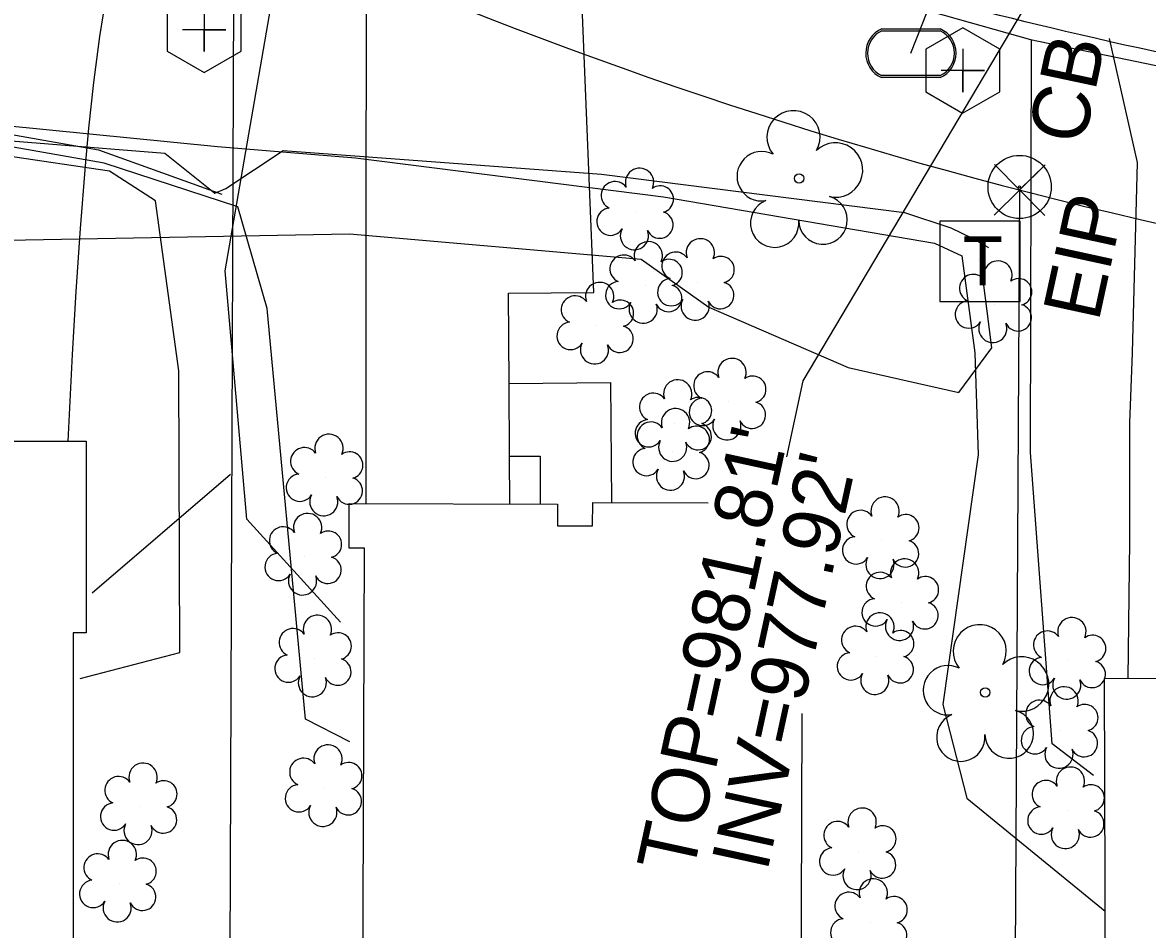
# Model space of a CAD drawing. Extents: x 1614427 to 1617186, y 896524 to 905462.
# Drawn here: x 1616409.1 to 1616487.6, y 901599.9 to 901663.2 of the extents above; entities that cross this region are included whole.
import ezdxf

# ---------------------------------------------------------------- set-up
doc = ezdxf.new("R2010")
doc.units = 0
for name, color, linetype in [('Exist Building', 7, 'Continuous'), ('Exist Other Culture Area Outline', 7, 'Continuous'), ('Exist Property Corner CELL', 7, 'Continuous'), ('Exist Property Iron Pin CELL', 7, 'Continuous'), ('Exist Property Iron Pin Text', 7, 'Continuous'), ('Exist Property Line', 7, 'Continuous'), ('Exist Right of Way Line', 7, 'Continuous'), ('Exist Roads Curbs', 7, 'Continuous'), ('Exist Roads EOP', 7, 'Continuous'), ('Exist Roads EOP Other', 7, 'Continuous'), ('Exist Structure Minor Catch Basin Leader', 7, 'Continuous'), ('Exist Structure Minor Catch Basin Text', 7, 'Continuous'), ('Exist Structure Minor Catch Basin Top Elevation', 7, 'Continuous'), ('Exist Structure Minor Pipes RCP 18 Inch Invert', 7, 'Continuous'), ('Exist Utilities Gas UG Line SUE LOS B', 7, 'Continuous'), ('Exist Utilities Power UG Cable SUE LOS B', 7, 'Continuous'), ('Exist Utilities Sanitary Sewer Clean-Out CELL', 7, 'Continuous'), ('Exist Utilities Telephone Pedestal CELL', 7, 'Continuous'), ('Exist Utilities Telephone UG FO SUE LOS B', 7, 'Continuous'), ('Exist Utilities TV UG Cable SUE LOS B', 7, 'Continuous'), ('Exist Utilities Water Meter CELL', 7, 'Continuous'), ('Exist Utilities Water UG Line SUE LOS B', 7, 'Continuous'), ('Exist Vegetation Shrub CELL', 7, 'Continuous'), ('Exist Vegetation Tree CELL', 7, 'Continuous')]:
    doc.layers.add(name, color=color, linetype=linetype)

# ---------------------------------------------------------------- blocks, each defined once
blk = doc.blocks.new('EXIST PROPERTY IRON PIN')
at = {"layer": 'Exist Property Iron Pin CELL'}
for radius in [0.0441, 0.00141]:
    blk.add_circle((0, 0), radius, dxfattribs=at)
blk = doc.blocks.new('EXIST UTILITIES SANITARY SEWER CLEAN-OUT')
at = {"layer": 'Exist Utilities Sanitary Sewer Clean-Out CELL'}
blk.add_line((0, 0), (0, 0), dxfattribs=at)
blk.add_lwpolyline([(-0.0516, 0.0299), (-0.0517, -0.0297), (-0.0001, -0.0596), (0.0516, -0.0299), (0.0517, 0.0297), (0.0001, 0.0596)], close=True, dxfattribs=at)
blk.add_lwpolyline([(0, 0.0302), (0, -0.0302), (0, 0), (0.0302, 0), (-0.0302, 0)], dxfattribs=at)
blk = doc.blocks.new('EXIST UTILITIES TELEPHONE PEDESTAL')
at = {"layer": 'Exist Utilities Telephone Pedestal CELL'}
blk.add_line((0, 0), (0, 0), dxfattribs=at)
blk.add_lwpolyline([(-0.0545, -0.0565), (0.0574, -0.0565), (0.0574, 0.0554), (-0.0545, 0.0554), (-0.0545, -0.0565)], dxfattribs=at)
blk.add_text('T', height=0.0684, dxfattribs=at).set_placement((-0.0226, -0.0343))
blk = doc.blocks.new('EXIST UTILITIES WATER METER')
at = {"layer": 'Exist Utilities Water Meter CELL'}
blk.add_line((0, 0), (0, 0), dxfattribs=at)
for points in [[(-0.0408, 0.034), (0.0408, 0.034)], [(-0.0408, 0.0312), (0.0408, 0.0312)], [(0.0408, -0.0312), (-0.0413, -0.0312)], [(0.0408, -0.034), (-0.0413, -0.034)]]:
    blk.add_lwpolyline(points, dxfattribs=at)
for centre, radius, start, end in [((-0.0261, -0.0001), 0.0371, 113.178, 245.9794), ((0.0259, 0), 0.0371, 293.6483, 66.3084), ((-0.0259, -0.0001), 0.0347, 115.3009, 243.7824), ((0.0261, 0), 0.0345, 295.1272, 64.8728)]:
    blk.add_arc(centre, radius, start, end, dxfattribs=at)

msp = doc.modelspace()

# ---------------------------------------------------------------- linework, layer by layer
at = {"layer": 'Exist Building'}
for points in [[(1616394.898, 901627.651), (1616398.83, 901627.651), (1616398.829, 901633.968), (1616413.521, 901633.969), (1616413.522, 901620.575), (1616412.606, 901620.575), (1616412.608, 901591.698), (1616385.935, 901591.696), (1616385.933, 901610.332)], [(1616463.489, 901614.953), (1616463.395, 901587.068), (1616457.292, 901587.088), (1616457.264, 901578.691), (1616431.849, 901578.776), (1616431.883, 901588.687), (1616432.819, 901588.684), (1616432.946, 901626.485), (1616431.868, 901626.489), (1616431.878, 901629.618), (1616446.423, 901629.569), (1616446.418, 901628.051), (1616448.876, 901628.043), (1616448.881, 901629.683), (1616456.949, 901629.656)]]:
    msp.add_lwpolyline(points, dxfattribs=at)
msp.add_lwpolyline([(1616517.458, 901617.54), (1616517.599, 901573.704), (1616484.754, 901573.599), (1616484.614, 901617.397), (1616496.062, 901617.434), (1616496.048, 901621.76), (1616517.306, 901621.828), (1616517.32, 901617.539)], close=True, dxfattribs=at)
at = {"layer": 'Exist Other Culture Area Outline'}
for points in [[(1616443.048, 901637.997), (1616450.123, 901638.046), (1616450.194, 901629.679)], [(1616443.075, 901632.906), (1616445.208, 901632.905), (1616445.224, 901629.573)]]:
    msp.add_lwpolyline(points, dxfattribs=at)
at = {"layer": 'Exist Property Corner CELL'}
msp.add_line((1616478.69, 901651.495), (1616478.69, 901651.495), dxfattribs=at)
msp.add_lwpolyline([(1616476.932, 901653.273), (1616480.448, 901649.717), (1616478.69, 901651.495), (1616480.467, 901653.253), (1616476.912, 901649.737)], dxfattribs=at)
at = {"layer": 'Exist Property Line'}
for p, q in [((1616423.205, 901496.843), (1616423.837, 901670.831)), ((1616478.69, 901651.495), (1616477.825, 901496.627))]:
    msp.add_line(p, q, dxfattribs=at)
at = {"layer": 'Exist Right of Way Line'}
msp.add_arc((1616560.484, 901967.642), 326.557, 246.2087, 268.51667, dxfattribs=at)
at = {"layer": 'Exist Roads Curbs'}
msp.add_spline([(1616576.436, 901651.141), (1616560.362, 901651.873), (1616541.572, 901653.197), (1616514.262, 901656.474), (1616480.87, 901662.803), (1616452.549, 901670.884), (1616427.974, 901679.501)], degree=3, dxfattribs=at)
at = {"layer": 'Exist Roads EOP'}
msp.add_spline([(1616600.703, 901615.071), (1616596.491, 901640.707), (1616577.816, 901651.88), (1616577.758, 901653.582), (1616560.382, 901654.399), (1616541.66, 901655.742), (1616514.624, 901658.966), (1616481.568, 901665.456), (1616453.293, 901673.284), (1616429.007, 901681.848), (1616427.559, 901682.356), (1616413.543, 901687.442), (1616400.429, 901690.536), (1616382.846, 901691.642), (1616359.811, 901688.156), (1616349.758, 901685.257), (1616334.537, 901681.299), (1616320.225, 901678.765)], degree=3, dxfattribs=at)
at = {"layer": 'Exist Roads EOP Other'}
for points in [[(1616412.253, 901633.969), (1616412.563, 901640.017), (1616412.82, 901644.408), (1616413.119, 901648.794), (1616413.462, 901653.175), (1616413.689, 901655.803), (1616414.047, 901659.005), (1616414.479, 901662.199), (1616414.984, 901665.385), (1616415.561, 901668.56), (1616416.086, 901671.026)], [(1616433.067, 901629.614), (1616433.076, 901644.726), (1616433.098, 901669.403)], [(1616443.093, 901629.58), (1616443.075, 901632.906), (1616443.048, 901637.997), (1616443.015, 901644.283), (1616448.973, 901644.349), (1616448.154, 901664.293)], [(1616486.283, 901617.402), (1616486.381, 901626.996), (1616486.398, 901635.24), (1616486.564, 901640.136), (1616486.917, 901653.403), (1616484.967, 901662.054)]]:
    msp.add_lwpolyline(points, dxfattribs=at)
at = {"layer": 'Exist Structure Minor Catch Basin Leader'}
msp.add_lwpolyline([(1616479.393, 901664.827), (1616463.567, 901638.167), (1616462.425, 901632.862)], dxfattribs=at)
at = {"layer": 'Exist Utilities Gas UG Line SUE LOS B'}
msp.add_line((1616413.941, 901623.385), (1616423.596, 901631.665), dxfattribs=at)
for points in [[(1616326.476, 901676.736), (1616348.676, 901680.409), (1616373.137, 901686.793), (1616383.025, 901688.182), (1616402.076, 901686.65), (1616424.003, 901679.778), (1616450.549, 901670.159), (1616479.448, 901661.996), (1616512.172, 901655.218), (1616540.791, 901649.287), (1616561.301, 901640.128), (1616569.634, 901633.987), (1616582.757, 901628.459), (1616598.916, 901622.957)], [(1616431.279, 901621.331), (1616424.74, 901628.52), (1616423.23, 901645.841), (1616426.723, 901666.015), (1616429.548, 901678.085)], [(1616483.844, 901610.622), (1616480.965, 901612.831), (1616479.461, 901633.18), (1616479.526, 901661.974)]]:
    msp.add_lwpolyline(points, dxfattribs=at)
at = {"layer": 'Exist Utilities Power UG Cable SUE LOS B'}
for points in [[(1616431.929, 901612.971), (1616428.819, 901614.563), (1616426.151, 901643.219), (1616424.095, 901650.319), (1616414.764, 901653.361), (1616392.769, 901657.217), (1616371.385, 901660.505), (1616355.218, 901660.133), (1616340.06, 901657.556), (1616322.037, 901656.408)], [(1616322.129, 901656.828), (1616339.438, 901657.54), (1616355.254, 901660.311), (1616371.586, 901660.692), (1616392.859, 901657.485), (1616422.684, 901654.528), (1616432.316, 901653.731), (1616453.833, 901651.02), (1616472.739, 901647.791), (1616474.659, 901646.901), (1616475.563, 901640.136), (1616475.797, 901633.012), (1616473.32, 901615.576), (1616475.015, 901609.049), (1616484.66, 901601.148)], [(1616413.087, 901617.407), (1616420.044, 901619.219), (1616419.981, 901638.866), (1616418.361, 901650.741), (1616415.145, 901652.817), (1616393.412, 901656.01), (1616371.662, 901659.29), (1616355.743, 901659.03), (1616340.12, 901656.384), (1616321.804, 901655.34)]]:
    msp.add_lwpolyline(points, dxfattribs=at)
at = {"layer": 'Exist Utilities Telephone UG FO SUE LOS B'}
msp.add_lwpolyline([(1616320.939, 901651.383), (1616362.887, 901649.358), (1616380.365, 901647.483), (1616431.909, 901648.438), (1616452.27, 901646.672), (1616456.985, 901643.309), (1616466.723, 901639.114), (1616474.447, 901637.354), (1616476.764, 901640.469), (1616475.96, 901646.691)], dxfattribs=at)
at = {"layer": 'Exist Utilities TV UG Cable SUE LOS B'}
for points in [[(1616322.594, 901658.961), (1616339.795, 901659.859), (1616360.734, 901661.282), (1616382.487, 901659.929), (1616414.384, 901654.293), (1616422.982, 901651.209)], [(1616322.652, 901659.227), (1616355.195, 901661.085), (1616371.732, 901661.161), (1616395.914, 901657.717), (1616402.743, 901655.366), (1616419.005, 901654.07), (1616422.504, 901651.267), (1616423.268, 901651.588), (1616427.27, 901654.253), (1616449.491, 901652.608), (1616470.665, 901649.916), (1616473.894, 901648.847), (1616475.375, 901648.133), (1616476.522, 901647.481)]]:
    msp.add_lwpolyline(points, dxfattribs=at)
at = {"layer": 'Exist Utilities Water UG Line SUE LOS B'}
msp.add_line((1616471.106, 901661.04), (1616476.068, 901673.701), dxfattribs=at)
at = {"layer": 'Exist Vegetation Shrub CELL'}
for p, q in [((1616451.925, 901649.987), (1616451.925, 901649.987)), ((1616452.538, 901644.858), (1616452.538, 901644.858)), ((1616456.17, 901645.065), (1616456.17, 901645.065)), ((1616476.949, 901643.511), (1616476.949, 901643.511)), ((1616449.139, 901642.015), (1616449.139, 901642.015)), ((1616458.382, 901636.712), (1616458.382, 901636.712)), ((1616454.597, 901635.219), (1616454.597, 901635.219)), ((1616454.44, 901633.208), (1616454.44, 901633.208)), ((1616430.237, 901631.422), (1616430.237, 901631.422)), ((1616469.071, 901627.042), (1616469.071, 901627.042)), ((1616428.752, 901625.891), (1616428.752, 901625.891)), ((1616470.436, 901622.719), (1616470.436, 901622.719)), ((1616429.436, 901618.791), (1616429.436, 901618.791)), ((1616468.712, 901618.953), (1616468.712, 901618.953)), ((1616482.113, 901618.625), (1616482.113, 901618.625)), ((1616481.566, 901613.794), (1616481.566, 901613.794)), ((1616430.171, 901609.741), (1616430.171, 901609.741)), ((1616417.264, 901608.467), (1616417.264, 901608.467)), ((1616482.01, 901608.189), (1616482.01, 901608.189)), ((1616467.47, 901605.329), (1616467.47, 901605.329)), ((1616415.807, 901603.07), (1616415.807, 901603.07)), ((1616468.25, 901600.387), (1616468.25, 901600.387))]:
    msp.add_line(p, q, dxfattribs=at)
for centre, radius, start, end in [((1616452.154, 901652.027), 0.99, 334.83907, 200.47174), ((1616450.442, 901651.114), 0.968, 35.89076, 245.42165), ((1616453.597, 901650.856), 0.929, 284.45672, 126.08612), ((1616450.124, 901649.282), 0.955, 95.10992, 327.95341), ((1616453.562, 901649.058), 0.937, 204.99133, 73.46012), ((1616451.796, 901648.303), 0.984, 151.27966, 21.38702), ((1616452.766, 901646.899), 0.99, 334.83907, 200.47174), ((1616456.398, 901647.106), 0.99, 334.83907, 200.47174), ((1616454.687, 901646.192), 0.968, 35.89076, 245.42165), ((1616451.055, 901645.985), 0.968, 35.89076, 245.42165), ((1616454.21, 901645.727), 0.929, 284.45672, 126.08612), ((1616457.842, 901645.934), 0.929, 284.45672, 126.08612), ((1616477.178, 901645.551), 0.99, 334.83907, 200.47174), ((1616475.467, 901644.637), 0.968, 35.89076, 245.42165), ((1616449.368, 901644.056), 0.99, 334.83907, 200.47174), ((1616450.737, 901644.154), 0.955, 95.10992, 327.95341), ((1616454.175, 901643.929), 0.937, 204.99133, 73.46012), ((1616454.369, 901644.361), 0.955, 95.10992, 327.95341), ((1616457.807, 901644.136), 0.937, 204.99133, 73.46012), ((1616478.621, 901644.379), 0.929, 284.45672, 126.08612), ((1616447.656, 901643.142), 0.968, 35.89076, 245.42165), ((1616450.811, 901642.884), 0.929, 284.45672, 126.08612), ((1616452.409, 901643.175), 0.984, 151.27966, 21.38702), ((1616456.041, 901643.382), 0.984, 151.27966, 21.38702), ((1616475.149, 901642.806), 0.955, 95.10992, 327.95341), ((1616478.586, 901642.582), 0.937, 204.99133, 73.46012), ((1616447.339, 901641.311), 0.955, 95.10992, 327.95341), ((1616450.776, 901641.086), 0.937, 204.99133, 73.46012), ((1616476.821, 901641.827), 0.984, 151.27966, 21.38702), ((1616449.01, 901640.332), 0.984, 151.27966, 21.38702), ((1616458.61, 901638.752), 0.99, 334.83907, 200.47174), ((1616456.899, 901637.838), 0.968, 35.89076, 245.42165), ((1616460.054, 901637.581), 0.929, 284.45672, 126.08612), ((1616454.826, 901637.26), 0.99, 334.83907, 200.47174), ((1616453.114, 901636.346), 0.968, 35.89076, 245.42165), ((1616456.581, 901636.007), 0.955, 95.10992, 327.95341), ((1616456.269, 901636.088), 0.929, 284.45672, 126.08612), ((1616454.668, 901635.248), 0.99, 334.83907, 200.47174), ((1616460.019, 901635.783), 0.937, 204.99133, 73.46012), ((1616452.796, 901634.515), 0.955, 95.10992, 327.95341), ((1616452.957, 901634.335), 0.968, 35.89076, 245.42165), ((1616458.253, 901635.028), 0.984, 151.27966, 21.38702), ((1616456.234, 901634.29), 0.937, 204.99133, 73.46012), ((1616456.112, 901634.077), 0.929, 284.45672, 126.08612), ((1616430.466, 901633.462), 0.99, 334.83907, 200.47174), ((1616454.468, 901633.536), 0.984, 151.27966, 21.38702), ((1616428.755, 901632.548), 0.968, 35.89076, 245.42165), ((1616431.909, 901632.291), 0.929, 284.45672, 126.08612), ((1616452.639, 901632.503), 0.955, 95.10992, 327.95341), ((1616456.077, 901632.279), 0.937, 204.99133, 73.46012), ((1616428.437, 901630.717), 0.955, 95.10992, 327.95341), ((1616431.874, 901630.493), 0.937, 204.99133, 73.46012), ((1616454.311, 901631.524), 0.984, 151.27966, 21.38702), ((1616430.109, 901629.738), 0.984, 151.27966, 21.38702), ((1616469.3, 901629.083), 0.99, 334.83907, 200.47174), ((1616467.589, 901628.169), 0.968, 35.89076, 245.42165), ((1616428.981, 901627.931), 0.99, 334.83907, 200.47174), ((1616470.743, 901627.911), 0.929, 284.45672, 126.08612), ((1616427.27, 901627.018), 0.968, 35.89076, 245.42165), ((1616430.424, 901626.76), 0.929, 284.45672, 126.08612), ((1616467.271, 901626.338), 0.955, 95.10992, 327.95341), ((1616470.709, 901626.113), 0.937, 204.99133, 73.46012), ((1616426.952, 901625.187), 0.955, 95.10992, 327.95341), ((1616430.389, 901624.962), 0.937, 204.99133, 73.46012), ((1616468.943, 901625.359), 0.984, 151.27966, 21.38702), ((1616470.665, 901624.759), 0.99, 334.83907, 200.47174), ((1616428.624, 901624.207), 0.984, 151.27966, 21.38702), ((1616468.953, 901623.845), 0.968, 35.89076, 245.42165), ((1616472.108, 901623.588), 0.929, 284.45672, 126.08612), ((1616468.636, 901622.014), 0.955, 95.10992, 327.95341), ((1616468.941, 901620.993), 0.99, 334.83907, 200.47174), ((1616472.073, 901621.79), 0.937, 204.99133, 73.46012), ((1616429.665, 901620.832), 0.99, 334.83907, 200.47174), ((1616470.308, 901621.035), 0.984, 151.27966, 21.38702), ((1616482.342, 901620.665), 0.99, 334.83907, 200.47174), ((1616427.954, 901619.918), 0.968, 35.89076, 245.42165), ((1616431.108, 901619.66), 0.929, 284.45672, 126.08612), ((1616467.23, 901620.08), 0.968, 35.89076, 245.42165), ((1616470.384, 901619.822), 0.929, 284.45672, 126.08612), ((1616480.631, 901619.751), 0.968, 35.89076, 245.42165), ((1616483.785, 901619.493), 0.929, 284.45672, 126.08612), ((1616427.636, 901618.087), 0.955, 95.10992, 327.95341), ((1616466.912, 901618.248), 0.955, 95.10992, 327.95341), ((1616470.349, 901618.024), 0.937, 204.99133, 73.46012), ((1616480.313, 901617.92), 0.955, 95.10992, 327.95341), ((1616431.074, 901617.862), 0.937, 204.99133, 73.46012), ((1616483.75, 901617.696), 0.937, 204.99133, 73.46012), ((1616429.308, 901617.108), 0.984, 151.27966, 21.38702), ((1616468.584, 901617.269), 0.984, 151.27966, 21.38702), ((1616481.985, 901616.941), 0.984, 151.27966, 21.38702), ((1616481.795, 901615.834), 0.99, 334.83907, 200.47174), ((1616480.083, 901614.92), 0.968, 35.89076, 245.42165), ((1616483.238, 901614.663), 0.929, 284.45672, 126.08612), ((1616479.766, 901613.089), 0.955, 95.10992, 327.95341), ((1616483.203, 901612.865), 0.937, 204.99133, 73.46012), ((1616430.4, 901611.781), 0.99, 334.83907, 200.47174), ((1616481.438, 901612.11), 0.984, 151.27966, 21.38702), ((1616428.689, 901610.868), 0.968, 35.89076, 245.42165), ((1616417.492, 901610.507), 0.99, 334.83907, 200.47174), ((1616431.843, 901610.61), 0.929, 284.45672, 126.08612), ((1616482.239, 901610.23), 0.99, 334.83907, 200.47174), ((1616415.781, 901609.593), 0.968, 35.89076, 245.42165), ((1616418.936, 901609.336), 0.929, 284.45672, 126.08612), ((1616480.527, 901609.316), 0.968, 35.89076, 245.42165), ((1616428.371, 901609.037), 0.955, 95.10992, 327.95341), ((1616431.808, 901608.812), 0.937, 204.99133, 73.46012), ((1616483.682, 901609.058), 0.929, 284.45672, 126.08612), ((1616415.463, 901607.762), 0.955, 95.10992, 327.95341), ((1616418.901, 901607.538), 0.937, 204.99133, 73.46012), ((1616430.043, 901608.057), 0.984, 151.27966, 21.38702), ((1616467.699, 901607.37), 0.99, 334.83907, 200.47174), ((1616480.21, 901607.485), 0.955, 95.10992, 327.95341), ((1616483.647, 901607.26), 0.937, 204.99133, 73.46012), ((1616417.135, 901606.783), 0.984, 151.27966, 21.38702), ((1616465.987, 901606.456), 0.968, 35.89076, 245.42165), ((1616469.142, 901606.198), 0.929, 284.45672, 126.08612), ((1616481.882, 901606.505), 0.984, 151.27966, 21.38702), ((1616416.035, 901605.11), 0.99, 334.83907, 200.47174), ((1616465.67, 901604.625), 0.955, 95.10992, 327.95341), ((1616414.324, 901604.197), 0.968, 35.89076, 245.42165), ((1616417.479, 901603.939), 0.929, 284.45672, 126.08612), ((1616469.107, 901604.4), 0.937, 204.99133, 73.46012), ((1616467.341, 901603.645), 0.984, 151.27966, 21.38702), ((1616414.006, 901602.366), 0.955, 95.10992, 327.95341), ((1616468.479, 901602.427), 0.99, 334.83907, 200.47174), ((1616417.444, 901602.141), 0.937, 204.99133, 73.46012), ((1616466.767, 901601.513), 0.968, 35.89076, 245.42165), ((1616415.678, 901601.386), 0.984, 151.27966, 21.38702), ((1616469.922, 901601.256), 0.929, 284.45672, 126.08612), ((1616466.449, 901599.682), 0.955, 95.10992, 327.95341), ((1616469.887, 901599.458), 0.937, 204.99133, 73.46012)]:
    msp.add_arc(centre, radius, start, end, dxfattribs=at)
at = {"layer": 'Exist Vegetation Tree CELL'}
for p, q in [((1616463.292, 901652.298), (1616463.292, 901652.298)), ((1616476.291, 901616.425), (1616476.291, 901616.425))]:
    msp.add_line(p, q, dxfattribs=at)
for centre in [(1616463.292, 901652.298), (1616476.291, 901616.425)]:
    msp.add_circle(centre, 0.326, dxfattribs=at)
for centre, radius, start, end in [((1616462.907, 901655.172), 1.856, 330.16508, 219.71335), ((1616460.687, 901652.452), 1.727, 62.66361, 279.3457), ((1616465.841, 901652.887), 1.899, 257.1011, 134.19993), ((1616464.965, 901649.399), 1.698, 181.28216, 74.55999), ((1616461.588, 901649.178), 1.689, 111.56708, 6.23104), ((1616475.906, 901619.298), 1.856, 330.16508, 219.71335), ((1616478.84, 901617.013), 1.899, 257.1011, 134.19993), ((1616473.686, 901616.579), 1.727, 62.66361, 279.3457), ((1616474.587, 901613.304), 1.689, 111.56708, 6.23104), ((1616477.964, 901613.525), 1.698, 181.28216, 74.55999)]:
    msp.add_arc(centre, radius, start, end, dxfattribs=at)

# ---------------------------------------------------------------- block references
at = {"layer": 'Exist Property Iron Pin CELL', "xscale": 50, "yscale": 50}
msp.add_blockref('EXIST PROPERTY IRON PIN', (1616478.691, 901651.705), dxfattribs=at)
at = {"layer": 'Exist Utilities Sanitary Sewer Clean-Out CELL', "xscale": 50, "yscale": 50}
for p in [(1616421.75, 901662.667), (1616474.72, 901659.836)]:
    msp.add_blockref('EXIST UTILITIES SANITARY SEWER CLEAN-OUT', p, dxfattribs=at)
at = {"layer": 'Exist Utilities Telephone Pedestal CELL', "xscale": 50, "yscale": 50}
msp.add_blockref('EXIST UTILITIES TELEPHONE PEDESTAL', (1616475.856, 901646.545), dxfattribs=at)
at = {"layer": 'Exist Utilities Water Meter CELL', "xscale": 50, "yscale": 50}
msp.add_blockref('EXIST UTILITIES WATER METER', (1616471.106, 901661.04), dxfattribs=at)

# ---------------------------------------------------------------- texts
at = {"layer": 'Exist Property Iron Pin Text'}
msp.add_text('EIP', height=4, rotation=77.71667, dxfattribs=at).set_placement((1616484.201, 901642.226))
at = {"layer": 'Exist Structure Minor Catch Basin Text'}
msp.add_text('CB', height=4, rotation=78.01667, dxfattribs=at).set_placement((1616483.159, 901654.522))
at = {"layer": 'Exist Structure Minor Catch Basin Top Elevation'}
msp.add_text("TOP=981.81'", height=4, rotation=77.71667, dxfattribs=at).set_placement((1616455.852, 901603.6))
at = {"layer": 'Exist Structure Minor Pipes RCP 18 Inch Invert'}
msp.add_text("INV=977.92'", height=4, rotation=77.71667, dxfattribs=at).set_placement((1616461.063, 901603.828))

doc.saveas('drawing.dxf')
